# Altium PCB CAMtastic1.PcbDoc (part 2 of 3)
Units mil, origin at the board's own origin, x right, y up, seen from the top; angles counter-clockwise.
Board outline 2031.62 x 893.83 mil, 4 copper layers (Top Layer, Mid-Layer 1, Mid-Layer 2, Bottom Layer); 0 components, 63 nets, 248 pads, 0 vias.
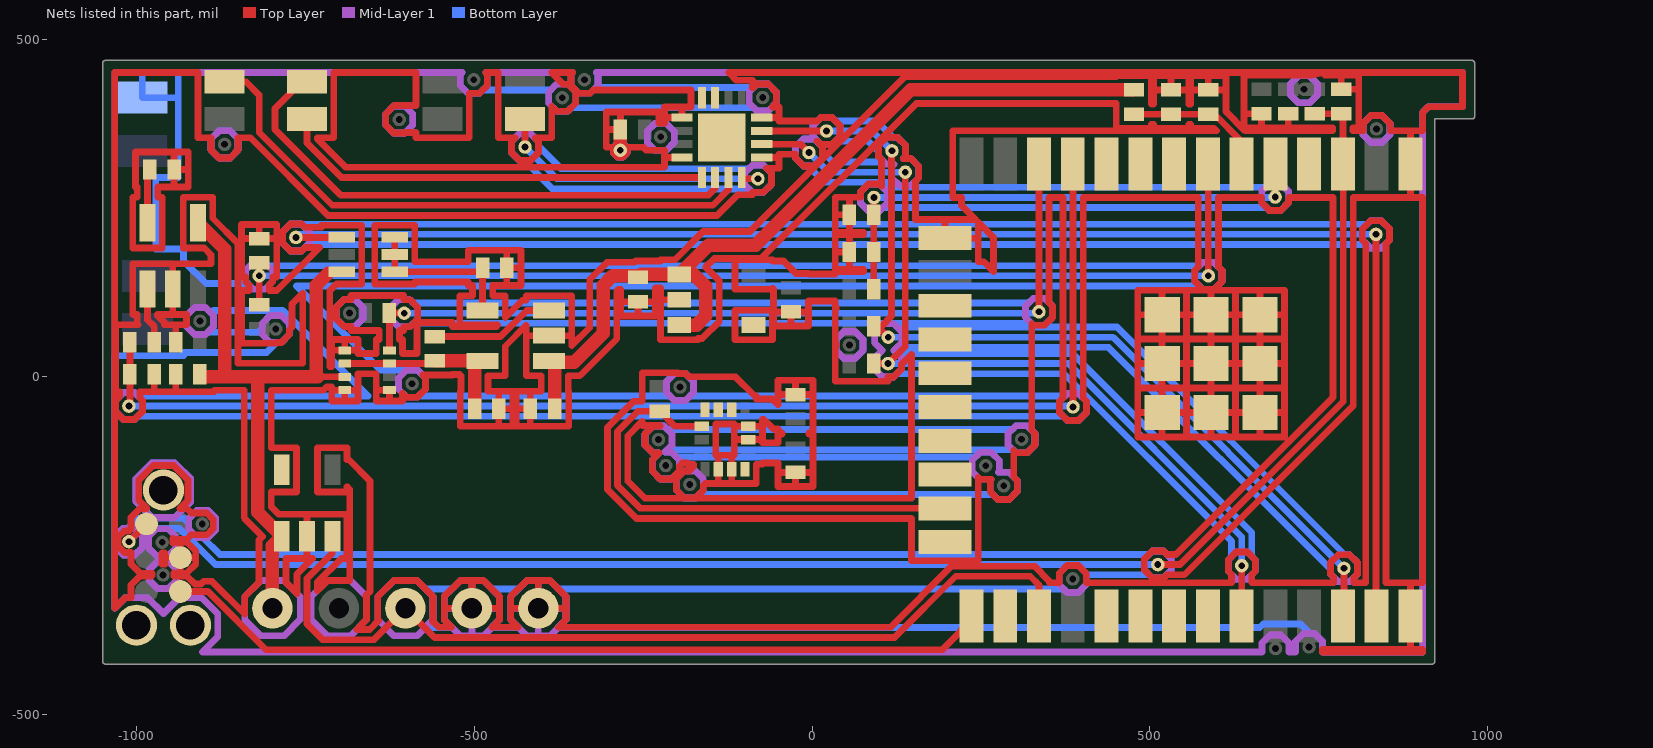
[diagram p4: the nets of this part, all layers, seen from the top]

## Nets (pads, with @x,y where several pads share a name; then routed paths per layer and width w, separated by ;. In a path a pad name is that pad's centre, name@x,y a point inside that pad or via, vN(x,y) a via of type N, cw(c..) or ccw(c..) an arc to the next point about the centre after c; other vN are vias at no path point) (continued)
$Net11: pad.1@55.12,184.98 pad.1@55.12,240.1 pad.1@196.46,205.31 pad.1@518.11,19.68 pad.1@518.11,92.13 pad.1@518.11,-52.76 pad.1@531.44,424.91 pad.1@586.55,424.91 pad.1@590.55,19.68 pad.1@590.55,92.13 pad.1@590.55,-52.76 pad.1@662.99,19.68 pad.1@662.99,92.13 pad.1@662.99,-52.76 pad.1@665.35,389.76 pad.1@704.72,389.76 pad.1@783.46,425.76 pad.1@885.83,314.96 pad.1@885.83,-354.33 pad.1@-24.8,-26.2 pad.1@-24.8,-141.51 pad.1@-31.5,96.17 pad.1@-74.8,324.8 pad.1@-74.8,383.86 pad.1@-94.49,-73.23 pad.1@-94.49,-92.91 pad.1@-119.29,-137.01 pad.1@-138.98,-137.01 pad.1@-192.91,324.8 pad.1@-192.91,383.86 pad.1@-196.85,114.17 pad.1@-257.87,111.13 pad.1@-284.03,366.14 pad.1@-284.16,335.43 pad.1@-389.76,61.02 pad.1@-405.51,-342.52 pad.1@-417.32,-47.24 pad.1@-452.19,161.42 pad.1@-464,-47.24 pad.1@-503.94,-342.52 pad.1@-625.98,-19.69 pad.1@-692.13,39.37 pad.1@-692.13,-19.69 pad.1@-748.03,-236.22 pad.1@-818.9,204.72 pad.1@-935.63,-267.72 pad.1@-942.55,3.94 pad.1@-942.55,51.18 pad.1@-944.88,307.09 pad.1@-946.85,129.92 pad.1@-974.18,3.94 pad.1@-992.13,413.39 | length 81681.8
  Top Layer w10: -974.18,-17.06 pad.1@-974.18,3.94 ; -953.56,-267.72 pad.1@-935.63,-267.72 ; -946.85,97.36 pad.1@-946.85,129.92 -946.85,162.48 ; -944.88,286.09 pad.1@-944.88,307.09 ; -944.88,328.09 pad.1@-944.88,307.09 ; -942.55,-17.06 pad.1@-942.55,3.94 ; pad.1@-942.55,51.18 -942.55,72.18 ; -935.63,-285.65 pad.1@-935.63,-267.72 ; -935.63,-249.79 pad.1@-935.63,-267.72 ; -928.88,307.09 pad.1@-944.88,307.09 ; -917.7,-267.72 pad.1@-935.63,-267.72 ; -890.08,335.98 -890.08,354.17 -909.61,354.17 -909.61,450.57 -1032.68,450.57 -1032.68,-342.47 -1017.41,-327.21 -1008.56,-327.21 -1008.56,-308.22 -995.13,-294.79 -978.26,-294.79 -977.23,-293.75 -977.23,-290.65 -995.13,-290.65 -1008.56,-277.21 -1008.56,-260.09 -1018.44,-260.09 -1027.81,-250.72 -1027.81,-237.47 -1018.44,-228.09 -1011.56,-228.09 -1008.56,-225.09 -1008.56,-208.22 -995.13,-194.79 -985.19,-194.79 -997.14,-182.84 -997.14,-152.59 -975.75,-131.21 -945.51,-131.21 -924.12,-152.59 -924.12,-182.84 -936.07,-194.79 -926.13,-194.79 -919.2,-201.72 -896.51,-201.72 -887.06,-211.16 -887.06,-224.42 -896.43,-233.79 -909.69,-233.79 -909.76,-233.72 -919.2,-233.72 -926.13,-240.65 -945.13,-240.65 -946.48,-239.29 -946.48,-246.14 -945.13,-244.79 -926.13,-244.79 -912.7,-258.22 -912.7,-277.21 -926.13,-290.65 -945.13,-290.65 -945.23,-290.55 -945.23,-294.89 -945.13,-294.79 -926.13,-294.79 -914.2,-306.72 -905.09,-306.72 -901.09,-302.72 -888.67,-302.72 -840.21,-351.17 -840.21,-325.54 -819.21,-304.54 -819.21,-241.72 -813.72,-236.22 -841.15,-208.78 -841.15,-20 -885.55,-20 -885.55,-22.06 -995.18,-22.06 -995.18,-31.65 -991.81,-35.02 -991.81,-51.59 -1003.53,-63.31 -1020.1,-63.31 -1031.81,-51.59 -1031.81,-35.02 -1025.18,-28.39 -1025.18,-22.06 -1031.18,-22.06 -1031.18,77.18 -998.21,77.18 -999.34,78.31 -999.34,92.36 -1006.06,92.36 -1006.06,167.48 -890.08,167.48 -890.08,180.69 -900.17,190.79 -931.26,190.79 -931.26,265.91 -887.64,265.91 -887.64,234.82 -850.08,197.26 -850.08,20 -754.46,20 -754.46,123.81 -770.31,107.95 -770.31,73.68 -774.34,69.65 -774.34,62.58 -786.05,50.87 -792.9,50.87 -792.9,49.87 -844.9,49.87 -844.9,127.87 -833.9,127.87 -833.9,136.32 -838.9,141.32 -838.9,147.72 -844.9,147.72 -844.9,225.72 -792.9,225.72 -792.9,147.72 -798.9,147.72 -798.9,141.32 -803.9,136.32 -803.9,127.87 -792.9,127.87 -792.9,127.79 -729.2,191.49 -751.22,191.49 -756.22,186.49 -772.78,186.49 -784.5,198.2 -784.5,214.77 -772.78,226.48 -756.22,226.48 -751.22,221.48 -726.53,221.48 -726.53,224.57 -667.17,224.57 -667.17,137.64 -704.16,137.64 -714.46,127.34 -714.46,15 -711.57,15 -711.57,55.28 -672.68,55.28 -672.68,34.68 -645.43,34.68 -645.43,55.28 -640.98,55.28 -640.98,68.49 -682.98,68.49 -682.98,74.49 -693.32,74.49 -705.04,86.2 -705.04,102.77 -693.32,114.49 -682.98,114.49 -682.98,120.49 -604.98,120.49 -604.98,114.25 -595.84,114.25 -584.13,102.53 -584.13,85.96 -595.84,74.25 -604.98,74.25 -604.98,68.49 -610.98,68.49 -610.98,55.28 -606.54,55.28 -606.54,34.68 -585.05,34.68 -585.05,80.62 -533.06,80.62 -533.06,74.7 -467.61,74.7 -465.7,76.61 -521.81,76.61 -521.81,120.24 -503.19,120.24 -503.19,135.42 -509.19,135.42 -509.19,140.51 -588.43,140.51 -588.43,137.64 -647.79,137.64 -647.79,224.57 -588.43,224.57 -588.43,170.51 -509.19,170.51 -509.19,187.42 -431.19,187.42 -431.19,135.42 -473.19,135.42 -473.19,120.24 -454.57,120.24 -454.57,87.75 -428.89,113.42 -423.39,113.42 -423.39,120.24 -356.14,120.24 -356.14,46.16 -329.44,72.86 -329.44,144.05 -303.89,169.61 -263.54,169.61 -261.57,171.57 -224.57,171.57 -224.57,173.39 -203.32,173.39 -161.49,215.21 -92.1,215.21 137.6,444.91 450.32,444.91 450.32,445.91 502.32,445.91 502.32,403.91 505.44,403.91 505.44,445.91 557.44,445.91 557.44,403.91 560.55,403.91 560.55,445.91 612.55,445.91 612.55,392.91 641.13,364.33 770.83,364.33 770.83,368.76 639.35,368.76 639.35,446.76 739.73,446.76 754.64,450.57 -123.51,450.57 -112.08,439.13 -88.43,439.13 -88.43,428.39 -86.93,428.39 -81.69,433.63 -65.12,433.63 -53.4,421.91 -53.4,405.34 -58.98,399.76 -49.06,399.76 -49.06,379.01 7.99,379.01 12.99,384.01 29.56,384.01 41.28,372.29 41.28,355.72 29.56,344.01 12.99,344.01 7.99,349.01 6.67,349.01 15.23,340.45 15.23,323.89 3.51,312.17 -13.06,312.17 -24.77,323.89 -24.77,329.49 -49.06,329.49 -49.06,308.9 -67.66,308.9 -60.36,301.6 -60.36,285.04 -72.08,273.32 -88.43,273.32 -88.43,269.53 -110.41,269.53 -140.89,239.05 -716.95,239.05 -832.08,354.17 -850.08,354.17 -850.08,352.55 ; -890.06,335.97 -878.35,324.25 -861.78,324.25 -850.06,335.97 -850.06,352.53 ; -839.9,204.72 pad.1@-818.9,204.72 ; -818.9,220.72 pad.1@-818.9,204.72 ; -797.9,204.72 pad.1@-818.9,204.72 ; -748.03,-263.86 pad.1@-748.03,-236.22 -748.03,-208.58 ; -706.57,-19.69 pad.1@-692.13,-19.69 ; -706.57,39.37 pad.1@-692.13,39.37 ; -692.13,-30.59 pad.1@-692.13,-19.69 ; -692.13,50.28 pad.1@-692.13,39.37 ; -677.68,-19.69 pad.1@-692.13,-19.69 ; -677.68,39.37 pad.1@-692.13,39.37 ; -640.43,-19.69 pad.1@-625.98,-19.69 -625.98,-30.59 ; -539.94,-342.52 pad.1@-503.94,-342.52 ; -503.94,-306.52 pad.1@-503.94,-342.52 ; -467.94,-342.52 pad.1@-503.94,-342.52 ; -464,-68.24 pad.1@-464,-47.24 ; -464,-26.24 pad.1@-464,-47.24 ; -452.19,140.42 pad.1@-452.19,161.42 ; -452.19,182.42 pad.1@-452.19,161.42 ; -448,-47.24 pad.1@-464,-47.24 ; -441.51,-342.52 pad.1@-405.51,-342.52 ; -436.19,161.42 pad.1@-452.19,161.42 ; -433.32,-47.24 pad.1@-417.32,-47.24 ; -418.39,61.02 pad.1@-389.76,61.02 -361.14,61.02 ; -417.32,-68.24 pad.1@-417.32,-47.24 ; -417.32,-26.24 pad.1@-417.32,-47.24 ; -405.51,-306.52 pad.1@-405.51,-342.52 ; -369.51,-342.52 pad.1@-405.51,-342.52 ; -300.03,366.14 pad.1@-284.03,366.14 -284.03,387.14 ; -278.87,111.13 pad.1@-257.87,111.13 ; -257.87,95.13 pad.1@-257.87,111.13 ; -236.87,111.13 pad.1@-257.87,111.13 ; -219.57,114.17 pad.1@-196.85,114.17 ; -213.66,324.8 pad.1@-192.91,324.8 ; -213.66,383.86 pad.1@-192.91,383.86 -192.91,394.76 ; -138.98,-152.83 pad.1@-138.98,-137.01 -138.98,-121.18 ; -119.29,-152.83 pad.1@-119.29,-137.01 -119.29,-121.18 ; -110.31,-92.91 pad.1@-94.49,-92.91 -78.66,-92.91 ; -110.31,-73.23 pad.1@-94.49,-73.23 -78.66,-73.23 ; pad.1@-74.8,324.8 -54.06,324.8 ; pad.1@-74.8,383.86 -54.06,383.86 ; -52.5,96.17 pad.1@-31.5,96.17 ; -45.8,-141.51 pad.1@-24.8,-141.51 ; -45.8,-26.2 pad.1@-24.8,-26.2 ; -31.5,80.17 pad.1@-31.5,96.17 ; -24.8,-157.51 pad.1@-24.8,-141.51 ; -24.8,-10.21 pad.1@-24.8,-26.2 ; -10.5,96.17 pad.1@-31.5,96.17 ; -3.8,-141.51 pad.1@-24.8,-141.51 ; -3.8,-26.2 pad.1@-24.8,-26.2 ; 39.12,184.98 pad.1@55.12,184.98 ; 39.12,240.1 pad.1@55.12,240.1 ; 55.12,163.98 pad.1@55.12,184.98 ; 55.12,205.98 pad.1@55.12,184.98 ; 55.12,219.1 pad.1@55.12,240.1 ; 55.12,261.1 pad.1@55.12,240.1 ; 196.46,228.03 pad.1@196.46,205.31 240.83,205.31 ; 486.93,-52.76 pad.1@518.11,-52.76 ; 486.93,19.68 pad.1@518.11,19.68 ; 486.93,92.13 pad.1@518.11,92.13 ; 510.44,424.91 pad.1@531.44,424.91 ; 518.11,-83.94 pad.1@518.11,-52.76 ; 518.11,-21.58 pad.1@518.11,-52.76 ; 518.11,-11.5 pad.1@518.11,19.68 ; 518.11,50.87 pad.1@518.11,19.68 ; 518.11,60.95 pad.1@518.11,92.13 ; 518.11,123.31 pad.1@518.11,92.13 ; 531.44,440.91 pad.1@531.44,424.91 ; 549.29,-52.76 pad.1@518.11,-52.76 ; 549.29,19.68 pad.1@518.11,19.68 ; 549.29,92.13 pad.1@518.11,92.13 ; 552.44,424.91 pad.1@531.44,424.91 ; 559.37,-52.76 pad.1@590.55,-52.76 ; 559.37,19.68 pad.1@590.55,19.68 ; 559.37,92.13 pad.1@590.55,92.13 ; 565.55,424.91 pad.1@586.55,424.91 ; 586.55,440.91 pad.1@586.55,424.91 ; 590.55,-83.94 pad.1@590.55,-52.76 ; 590.55,-21.58 pad.1@590.55,-52.76 ; 590.55,-11.5 pad.1@590.55,19.68 ; 590.55,50.87 pad.1@590.55,19.68 ; 590.55,60.95 pad.1@590.55,92.13 ; 590.55,123.31 pad.1@590.55,92.13 ; 607.55,424.91 pad.1@586.55,424.91 ; 621.73,-52.76 pad.1@590.55,-52.76 ; 621.73,19.68 pad.1@590.55,19.68 ; 621.73,92.13 pad.1@590.55,92.13 ; 631.81,-52.76 pad.1@662.99,-52.76 ; 631.81,19.68 pad.1@662.99,19.68 ; 631.81,92.13 pad.1@662.99,92.13 ; 644.35,389.76 pad.1@665.35,389.76 665.35,373.76 ; 662.99,-83.94 pad.1@662.99,-52.76 ; 662.99,-21.58 pad.1@662.99,-52.76 ; 662.99,-11.5 pad.1@662.99,19.68 ; 662.99,50.87 pad.1@662.99,19.68 ; 662.99,60.95 pad.1@662.99,92.13 ; 662.99,123.31 pad.1@662.99,92.13 ; 694.17,-52.76 pad.1@662.99,-52.76 ; 694.17,19.68 pad.1@662.99,19.68 ; 694.17,92.13 pad.1@662.99,92.13 ; 704.72,373.76 pad.1@704.72,389.76 ; 783.46,441.76 pad.1@783.46,425.76 804.46,425.76 ; 885.83,-398.7 pad.1@885.83,-354.33 885.83,-309.96 ; 885.83,270.59 pad.1@885.83,314.96 885.83,359.33 ; -1006.06,190.79 -1006.06,265.91 -999.25,265.91 -999.25,281.09 -1001.88,281.09 -1001.88,333.09 -923.88,333.09 -923.88,281.09 -969.25,281.09 -969.25,265.91 -962.44,265.91 -962.44,190.79 -1006.06,190.79 ; -969.34,90.74 -969.34,92.36 -926.55,92.36 -926.55,90.96 -926.55,77.18 -959.18,77.18 -959.18,80.58 -969.34,90.74 ; -962.79,-277.31 -962.7,-277.21 -962.7,-260.91 -958.56,-260.91 -958.56,-277.21 -958.47,-277.31 -962.79,-277.31 ; -801.15,-192.22 -801.15,-170.43 -763.62,-170.43 -763.62,-105.16 -801.15,-105.16 -801.15,-20 -724,-20 -719,-15 -711.57,-15 -711.57,-35.59 -672.68,-35.59 -672.68,4.69 -645.43,4.69 -645.43,-35.59 -606.54,-35.59 -606.54,-24.24 -600.75,-30.03 -584.18,-30.03 -572.46,-18.31 -572.46,-1.74 -576.83,2.62 -533.06,2.62 -533.06,3.62 -521.81,3.62 -521.81,1.81 -520,1.81 -520,-21.24 -521,-21.24 -521,-73.24 -443,-73.24 -443,-21.24 -480,-21.24 -480,1.81 -454.57,1.81 -454.57,45.32 -423.39,76.51 -423.39,1.81 -401.32,1.81 -401.32,-21.24 -438.32,-21.24 -438.32,-73.24 -360.32,-73.24 -360.32,-21.24 -361.32,-21.24 -361.32,1.65 -344.08,1.65 -289.44,56.29 -289.44,127.48 -287.32,129.61 -283.87,129.61 -283.87,90.13 -231.87,90.13 -231.87,131.58 -224.57,131.58 -224.57,54.96 -169.13,54.96 -169.13,56.77 -162.98,56.77 -137.48,82.27 -137.48,142.14 -157.74,162.4 -144.93,175.21 -75.53,175.21 154.17,404.91 450.32,404.91 450.32,403.91 450.32,367.91 502.32,367.91 502.32,373.91 505.44,373.91 505.44,367.91 557.44,367.91 557.44,373.91 560.55,373.91 560.55,367.91 595.13,367.91 598.71,364.33 208.11,364.33 208.11,265.59 221.22,265.59 221.22,253.63 241.82,233.03 152.79,233.03 152.79,289.87 157.79,294.87 157.79,311.43 146.08,323.15 134.9,323.15 138.11,326.36 138.11,342.93 126.39,354.65 109.83,354.65 98.11,342.93 98.11,326.36 102.56,321.91 102.56,282.79 99.75,285.6 83.18,285.6 71.47,273.88 71.47,266.1 34.12,266.1 34.12,214.1 76.12,214.1 76.12,210.98 34.12,210.98 34.12,158.98 76.12,158.98 76.12,155.86 34.12,155.86 34.12,152.17 -5.5,152.17 -5.5,153.17 -24.21,153.17 -42.61,171.57 -58.9,171.57 -58.9,173.39 -114.33,173.39 -114.33,129.76 -58.9,129.76 -58.9,131.29 -57.5,129.89 -57.5,75.17 -5.5,75.17 -5.5,112.17 34.12,112.17 34.12,103.86 35.12,103.86 35.12,100.74 34.12,100.74 34.12,48.74 35.12,48.74 35.12,45.62 34.12,45.62 34.12,-6.37 112.12,-6.37 112.12,-0.37 120.61,-0.37 132.33,11.34 132.33,18.41 147.09,33.17 147.09,-179.69 -247.92,-179.69 -273.15,-154.46 -273.15,-87.39 -251.72,-65.96 -251.59,-65.96 -251.59,-71.96 -225.8,-71.96 -224.91,-72.85 -235.93,-72.85 -247.65,-84.56 -247.65,-101.13 -235.93,-112.85 -226.72,-112.85 -236.87,-122.99 -236.87,-139.56 -225.15,-151.27 -208.58,-151.27 -196.87,-139.56 -196.87,-132.49 -191.98,-127.6 -184.61,-127.6 -184.61,-129.49 -175.55,-129.49 -175.55,-132.68 -182.18,-139.32 -189.55,-139.32 -201.26,-151.03 -201.26,-167.6 -189.55,-179.32 -172.98,-179.32 -161.26,-167.6 -161.26,-160.82 -158.28,-157.83 -82.72,-157.83 -82.72,-129.49 -73.66,-129.49 -73.66,-127.6 -50.8,-127.6 -50.8,-162.51 1.2,-162.51 1.2,-84.51 -4.8,-84.51 -4.8,-83.2 1.2,-83.2 1.2,-5.21 -50.8,-5.21 -50.8,-41.23 -59.29,-32.75 -82.72,-32.75 -82.72,-27.99 -85.31,-27.99 -113.28,-0.01 -182.43,-0.01 -187.48,5.04 -199.59,5.04 -199.59,6.04 -251.59,6.04 -251.59,-35.96 -264.15,-35.96 -303.15,-74.96 -303.15,-166.88 -260.35,-209.68 147.09,-209.68 147.09,-272.4 245.83,-272.4 245.83,-148.92 248.62,-151.72 264.88,-151.72 263.46,-153.13 263.46,-169.7 275.18,-181.42 291.75,-181.42 303.46,-169.7 303.46,-153.13 298.46,-148.13 298.46,-109.16 301.75,-112.45 318.32,-112.45 330.04,-100.73 330.04,-84.16 325.04,-79.16 325.04,78.74 327.37,76.4 343.94,76.4 355.66,88.11 355.66,104.68 350.66,109.68 350.66,265.59 371.19,265.59 371.19,-31.18 366.19,-36.18 366.19,-52.75 377.91,-64.46 394.48,-64.46 406.19,-52.75 406.19,-36.18 401.19,-31.18 401.19,265.59 571.61,265.59 571.61,162.89 566.61,157.89 566.61,141.32 578.33,129.61 594.9,129.61 606.61,141.32 606.61,157.89 601.61,162.89 601.61,265.59 665.53,265.59 665.53,258.04 677.25,246.32 693.82,246.32 705.53,258.04 705.53,265.59 771.32,265.59 771.32,-30.3 538.62,-263 525.1,-263 520.1,-258 503.53,-258 491.81,-269.72 491.81,-286.29 503.53,-298 520.1,-298 525.1,-293 551.05,-293 801.32,-42.73 801.32,265.59 903.89,265.59 903.89,-304.96 849.65,-304.96 849.65,197.7 854.65,202.7 854.65,219.27 842.93,230.98 826.36,230.98 814.65,219.27 814.65,202.7 819.65,197.7 819.65,-304.96 802.4,-304.96 802.4,-296.75 807.4,-291.75 807.4,-275.18 795.69,-263.46 779.12,-263.46 767.4,-275.18 767.4,-291.75 772.4,-296.75 772.4,-304.96 651.01,-304.96 651.01,-292.81 656.01,-287.81 656.01,-271.24 644.3,-259.53 627.73,-259.53 616.02,-271.24 616.02,-287.81 621.02,-292.81 621.02,-304.96 405.83,-304.96 405.83,-290.93 394.11,-279.21 377.54,-279.21 365.83,-290.93 365.83,-304.96 350.83,-304.96 350.83,-302.05 329.05,-280.28 206.39,-280.28 115.83,-370.83 -375.84,-370.83 -364.51,-359.5 -364.51,-325.54 -388.53,-301.52 -422.49,-301.52 -446.51,-325.54 -446.51,-359.5 -435.19,-370.83 -474.26,-370.83 -462.94,-359.5 -462.94,-325.54 -486.95,-301.52 -520.92,-301.52 -544.94,-325.54 -544.94,-359.5 -533.61,-370.83 -552.84,-370.83 -562.76,-360.9 -561.36,-359.5 -561.36,-325.54 -585.38,-301.52 -619.34,-301.52 -643.36,-325.54 -643.36,-359.5 -641.96,-360.9 -655.21,-374.15 -674.44,-374.15 -659.79,-359.5 -659.79,-325.54 -661.19,-324.13 -654.74,-317.68 -654.74,-154.25 -686.19,-122.8 -688.82,-122.8 -688.82,-105.16 -732.44,-105.16 -732.44,-170.43 -688.82,-170.43 -688.82,-162.59 -684.74,-166.67 -684.74,-301.52 -717.77,-301.52 -733.03,-316.78 -733.03,-304.6 -697.29,-268.86 -688.82,-268.86 -688.82,-203.58 -789.79,-203.58 -801.15,-192.22 ; -779.21,-304.54 -779.21,-268.86 -739.72,-268.86 -763.03,-292.17 -763.03,-320.72 -779.21,-304.54 ; -733.03,352.67 -733.03,354.17 -708.5,354.17 -708.5,450.57 -586.77,450.57 -586.77,401.89 -619,401.89 -619.81,401.09 -631.52,389.37 -631.52,372.8 -619.81,361.09 -603.24,361.09 -602.44,361.89 -586.77,361.89 -586.77,354.17 -507.72,354.17 -507.72,419.92 -492.82,419.92 -481.11,431.63 -481.11,448.2 -483.47,450.57 -464.72,450.57 -464.72,354.17 -440.21,354.17 -440.21,353.61 -445.21,348.61 -445.21,332.04 -433.49,320.32 -416.92,320.32 -405.21,332.04 -405.21,348.61 -410.21,353.61 -410.21,354.17 -385.67,354.17 -385.67,400.69 -378.36,393.39 -361.79,393.39 -350.08,405.1 -350.08,421.67 -361.79,433.39 -368.87,433.39 -385.67,450.19 -385.67,450.57 -354.94,450.57 -357.31,448.2 -357.31,431.63 -345.59,419.92 -329.02,419.92 -324.02,424.92 -179.29,424.92 -179.29,399.76 -218.66,399.76 -218.66,375.38 -227.03,375.38 -227.03,392.14 -305.03,392.14 -305.03,340.14 -293.6,340.14 -294.16,339.58 -294.16,331.29 -288.3,325.43 -280.02,325.43 -274.16,331.29 -274.16,339.58 -274.73,340.14 -250.32,340.14 -245.55,335.38 -218.66,335.38 -218.66,310.28 -690.64,310.28 -733.03,352.67 ; -142.95,-116.18 -142.95,-69.65 -115.31,-69.65 -115.31,-90.12 -115.31,-116.18 -142.95,-116.18 ; -114.33,54.96 -114.33,98.58 -58.9,98.58 -58.9,54.96 -114.33,54.96 ; -73.66,-97.6 -73.66,-62.75 -71.71,-62.75 -61.65,-72.81 -57.26,-77.2 -50.8,-77.2 -50.8,-83.2 -44.8,-83.2 -44.8,-84.51 -50.8,-84.51 -50.8,-97.6 -73.66,-97.6 ; 245.83,170.39 245.83,229.02 268.46,206.39 268.46,156.03 254.1,170.39 245.83,170.39 ; 481.93,-88.94 554.29,-88.94 554.29,-16.58 481.93,-16.58 481.93,-88.94 ; 481.93,-16.5 554.29,-16.5 554.29,55.87 481.93,55.87 481.93,-16.5 ; 481.93,55.95 554.29,55.95 554.29,128.31 481.93,128.31 481.93,55.95 ; 554.37,-88.94 626.73,-88.94 626.73,-16.58 554.37,-16.58 554.37,-88.94 ; 554.37,-16.5 626.73,-16.5 626.73,55.87 554.37,55.87 554.37,-16.5 ; 554.37,55.95 626.73,55.95 626.73,128.31 554.37,128.31 554.37,55.95 ; 626.81,-88.94 699.17,-88.94 699.17,-16.58 626.81,-16.58 626.81,-88.94 ; 626.81,-16.5 699.17,-16.5 699.17,55.87 626.81,55.87 626.81,-16.5 ; 626.81,55.95 699.17,55.95 699.17,128.31 626.81,128.31 626.81,55.95 ; 755.7,-407.26 755.7,-403.7 903.89,-403.7 903.89,-407.26 755.7,-407.26 ; 756.65,450.57 962.94,450.57 962.94,399.83 912.09,399.83 903.89,391.63 903.89,364.33 855.83,364.33 855.83,375.11 855.5,375.44 843.79,387.15 827.22,387.15 815.5,375.44 815.5,364.33 800.83,364.33 800.83,368.76 809.46,368.76 809.46,446.76 759.01,446.76 756.65,450.57
  Top Layer w20: pad.1@-284.16,335.43 -284.03,335.56 pad.1@-284.03,366.14
  Mid-Layer 1 w10: -539.94,-342.52 pad.1@-503.94,-342.52 ; -503.94,-378.52 pad.1@-503.94,-342.52 ; -503.94,-306.52 pad.1@-503.94,-342.52 ; -467.94,-342.52 pad.1@-503.94,-342.52 ; -441.51,-342.52 pad.1@-405.51,-342.52 ; -405.51,-378.52 pad.1@-405.51,-342.52 ; -405.51,-306.52 pad.1@-405.51,-342.52 ; -369.51,-342.52 pad.1@-405.51,-342.52 ; -1032.68,-342.47 -1032.68,450.57 -518.74,450.57 -521.11,448.2 -521.11,431.63 -509.39,419.92 -492.82,419.92 -481.11,431.63 -481.11,448.2 -483.47,450.57 -354.94,450.57 -357.31,448.2 -357.31,431.63 -345.59,419.92 -329.02,419.92 -317.31,431.63 -317.31,448.2 -319.67,450.57 962.94,450.57 962.94,399.83 912.09,399.83 903.89,391.63 903.89,-407.26 755.7,-407.26 755.7,-391.55 743.99,-379.84 727.42,-379.84 715.7,-391.55 715.7,-407.26 706.04,-407.26 706.04,-393.99 694.33,-382.28 677.76,-382.28 666.04,-393.99 666.04,-407.26 -902.88,-407.26 -880.12,-384.5 -880.12,-350.94 -903.85,-327.21 -937.41,-327.21 -960.63,-350.42 -983.85,-327.21 -1017.41,-327.21 -1032.68,-342.47 ; -1031.81,-252.38 -1020.1,-264.09 -1003.53,-264.09 -991.81,-252.38 -991.81,-235.81 -1003.53,-224.09 -1020.1,-224.09 -1031.81,-235.81 -1031.81,-252.38 ; -1031.81,-51.59 -1020.1,-63.31 -1003.53,-63.31 -991.81,-51.59 -991.81,-35.02 -1003.53,-23.31 -1020.1,-23.31 -1031.81,-35.02 -1031.81,-51.59 ; -1001.14,-184.5 -977.41,-208.23 -943.85,-208.23 -920.12,-184.5 -920.12,-150.94 -943.85,-127.21 -977.41,-127.21 -1001.14,-150.94 -1001.14,-184.5 ; -982.48,-253.19 -970.76,-264.91 -954.19,-264.91 -942.48,-253.19 -942.48,-236.62 -954.19,-224.91 -970.76,-224.91 -982.48,-236.62 -982.48,-253.19 ; -981.23,-301.59 -969.51,-313.31 -952.94,-313.31 -941.23,-301.59 -941.23,-285.02 -952.94,-273.31 -969.51,-273.31 -981.23,-285.02 -981.23,-301.59 ; -926.55,74.39 -914.84,62.68 -898.27,62.68 -886.55,74.39 -886.55,90.96 -898.27,102.68 -914.84,102.68 -926.55,90.96 -926.55,74.39 ; -923.06,-226.08 -911.34,-237.79 -894.78,-237.79 -883.06,-226.08 -883.06,-209.51 -894.78,-197.79 -911.34,-197.79 -923.06,-209.51 -923.06,-226.08 ; -890.06,335.97 -878.35,324.25 -861.78,324.25 -850.06,335.97 -850.06,352.53 -861.78,364.25 -878.35,364.25 -890.06,352.53 -890.06,335.97 ; -840.21,-359.5 -816.2,-383.52 -782.23,-383.52 -758.21,-359.5 -758.21,-325.54 -782.23,-301.52 -816.2,-301.52 -840.21,-325.54 -840.21,-359.5 ; -838.9,141.32 -827.18,129.61 -810.61,129.61 -798.9,141.32 -798.9,157.89 -810.61,169.61 -827.18,169.61 -838.9,157.89 -838.9,141.32 ; -814.33,62.58 -802.62,50.87 -786.05,50.87 -774.34,62.58 -774.34,79.15 -786.05,90.87 -802.62,90.87 -814.33,79.15 -814.33,62.58 ; -784.5,198.2 -772.78,186.49 -756.22,186.49 -744.5,198.2 -744.5,214.77 -756.22,226.48 -772.78,226.48 -784.5,214.77 -784.5,198.2 ; -741.79,-359.5 -717.77,-383.52 -683.8,-383.52 -659.79,-359.5 -659.79,-325.54 -683.8,-301.52 -717.77,-301.52 -741.79,-325.54 -741.79,-359.5 ; -705.04,86.2 -693.32,74.49 -676.76,74.49 -665.04,86.2 -665.04,102.77 -676.76,114.49 -693.32,114.49 -705.04,102.77 -705.04,86.2 ; -643.36,-359.5 -619.34,-383.52 -585.38,-383.52 -561.36,-359.5 -561.36,-325.54 -585.38,-301.52 -619.34,-301.52 -643.36,-325.54 -643.36,-359.5 ; -631.52,372.8 -619.81,361.09 -603.24,361.09 -591.52,372.8 -591.52,389.37 -603.24,401.09 -619.81,401.09 -631.52,389.37 -631.52,372.8 ; -624.13,85.96 -612.41,74.25 -595.84,74.25 -584.13,85.96 -584.13,102.53 -595.84,114.25 -612.41,114.25 -624.13,102.53 -624.13,85.96 ; -612.46,-18.31 -600.75,-30.03 -584.18,-30.03 -572.46,-18.31 -572.46,-1.74 -584.18,9.97 -600.75,9.97 -612.46,-1.74 -612.46,-18.31 ; -544.94,-359.5 -520.92,-383.52 -486.95,-383.52 -462.94,-359.5 -462.94,-325.54 -486.95,-301.52 -520.92,-301.52 -544.94,-325.54 -544.94,-359.5 ; -446.51,-359.5 -422.49,-383.52 -388.53,-383.52 -364.51,-359.5 -364.51,-325.54 -388.53,-301.52 -422.49,-301.52 -446.51,-325.54 -446.51,-359.5 ; -445.21,332.04 -433.49,320.32 -416.92,320.32 -405.21,332.04 -405.21,348.61 -416.92,360.32 -433.49,360.32 -445.21,348.61 -445.21,332.04 ; -390.08,405.1 -378.36,393.39 -361.79,393.39 -350.08,405.1 -350.08,421.67 -361.79,433.39 -378.36,433.39 -390.08,421.67 -390.08,405.1 ; -294.16,331.29 -288.3,325.43 -280.02,325.43 -274.16,331.29 -274.16,339.58 -280.02,345.43 -288.3,345.43 -294.16,339.58 -294.16,331.29 ; -247.65,-101.13 -247.65,-84.56 -235.93,-72.85 -219.36,-72.85 -207.65,-84.56 -207.65,-101.13 -217.79,-111.27 -208.58,-111.27 -196.87,-122.99 -196.87,-139.56 -208.58,-151.27 -225.15,-151.27 -236.87,-139.56 -236.87,-122.99 -226.72,-112.85 -235.93,-112.85 -247.65,-101.13 ; -244.41,347.09 -232.69,335.38 -216.13,335.38 -204.41,347.09 -204.41,363.66 -216.13,375.38 -232.69,375.38 -244.41,363.66 -244.41,347.09 ; -215.71,-23.3 -204,-35.01 -187.43,-35.01 -175.71,-23.3 -175.71,-6.73 -187.43,4.99 -204,4.99 -215.71,-6.73 -215.71,-23.3 ; -201.26,-167.6 -189.55,-179.32 -172.98,-179.32 -161.26,-167.6 -161.26,-151.03 -172.98,-139.32 -189.55,-139.32 -201.26,-151.03 -201.26,-167.6 ; -100.36,285.04 -88.65,273.32 -72.08,273.32 -60.36,285.04 -60.36,301.6 -72.08,313.32 -88.65,313.32 -100.36,301.6 -100.36,285.04 ; -93.4,405.34 -81.69,393.63 -65.12,393.63 -53.4,405.34 -53.4,421.91 -65.12,433.63 -81.69,433.63 -93.4,421.91 -93.4,405.34 ; -24.77,323.89 -13.06,312.17 3.51,312.17 15.23,323.89 15.23,340.45 3.51,352.17 -13.06,352.17 -24.77,340.45 -24.77,323.89 ; 1.28,355.72 12.99,344.01 29.56,344.01 41.28,355.72 41.28,372.29 29.56,384.01 12.99,384.01 1.28,372.29 1.28,355.72 ; 35.12,38.96 46.83,27.24 63.4,27.24 75.12,38.96 75.12,55.53 63.4,67.24 46.83,67.24 35.12,55.53 35.12,38.96 ; 71.47,257.32 83.18,245.6 99.75,245.6 111.46,257.32 111.46,273.88 99.75,285.6 83.18,285.6 71.47,273.88 71.47,257.32 ; 92.33,11.34 92.33,27.91 103.69,39.27 92.48,50.48 92.48,67.05 104.2,78.77 120.76,78.77 132.48,67.05 132.48,50.48 121.12,39.12 132.33,27.91 132.33,11.34 120.61,-0.37 104.05,-0.37 92.33,11.34 ; 98.11,326.36 98.11,342.93 109.83,354.65 126.39,354.65 138.11,342.93 138.11,326.36 134.9,323.15 146.08,323.15 157.79,311.43 157.79,294.87 146.08,283.15 129.51,283.15 117.8,294.87 117.8,311.43 121.01,314.65 109.83,314.65 98.11,326.36 ; 236.91,-140 236.91,-123.43 248.62,-111.72 265.19,-111.72 276.91,-123.43 276.91,-140 275.49,-141.42 291.75,-141.42 303.46,-153.13 303.46,-169.7 291.75,-181.42 275.18,-181.42 263.46,-169.7 263.46,-153.13 264.88,-151.72 248.62,-151.72 236.91,-140 ; 290.04,-100.73 301.75,-112.45 318.32,-112.45 330.04,-100.73 330.04,-84.16 318.32,-72.45 301.75,-72.45 290.04,-84.16 290.04,-100.73 ; 315.66,88.11 327.37,76.4 343.94,76.4 355.66,88.11 355.66,104.68 343.94,116.4 327.37,116.4 315.66,104.68 315.66,88.11 ; 365.83,-307.5 377.54,-319.21 394.11,-319.21 405.83,-307.5 405.83,-290.93 394.11,-279.21 377.54,-279.21 365.83,-290.93 365.83,-307.5 ; 366.19,-52.75 377.91,-64.46 394.48,-64.46 406.19,-52.75 406.19,-36.18 394.48,-24.46 377.91,-24.46 366.19,-36.18 366.19,-52.75 ; 491.81,-286.29 503.53,-298 520.1,-298 531.81,-286.29 531.81,-269.72 520.1,-258 503.53,-258 491.81,-269.72 491.81,-286.29 ; 566.61,141.32 578.33,129.61 594.9,129.61 606.61,141.32 606.61,157.89 594.9,169.61 578.33,169.61 566.61,157.89 566.61,141.32 ; 616.02,-287.81 627.73,-299.53 644.3,-299.53 656.01,-287.81 656.01,-271.24 644.3,-259.53 627.73,-259.53 616.02,-271.24 616.02,-287.81 ; 665.53,258.04 677.25,246.32 693.82,246.32 705.53,258.04 705.53,274.61 693.82,286.32 677.25,286.32 665.53,274.61 665.53,258.04 ; 708.35,417.48 720.06,405.76 736.63,405.76 748.35,417.48 748.35,434.05 736.63,445.76 720.06,445.76 708.35,434.05 708.35,417.48 ; 767.4,-291.75 779.12,-303.46 795.69,-303.46 807.4,-291.75 807.4,-275.18 795.69,-263.46 779.12,-263.46 767.4,-275.18 767.4,-291.75 ; 814.65,202.7 826.36,190.98 842.93,190.98 854.65,202.7 854.65,219.27 842.93,230.98 826.36,230.98 814.65,219.27 814.65,202.7 ; 815.5,358.87 827.22,347.15 843.79,347.15 855.5,358.87 855.5,375.44 843.79,387.15 827.22,387.15 815.5,375.44 815.5,358.87
  Bottom Layer w10: -992.13,448.01 pad.1@-992.13,413.39 -943.72,413.39 ; -539.94,-342.52 pad.1@-503.94,-342.52 -467.94,-342.52 ; -441.51,-342.52 pad.1@-405.51,-342.52 -369.51,-342.52 ; -1032.68,-342.47 -1032.68,31.24 -930.85,31.24 -930.85,36.18 -807.81,36.18 -793.12,50.87 -786.05,50.87 -774.34,62.58 -774.34,79.15 -786.05,90.87 -802.62,90.87 -814.33,79.15 -814.33,72.08 -820.23,66.18 -894.77,66.18 -886.55,74.39 -886.55,98.11 -783.87,98.11 -657.46,-28.31 -998.53,-28.31 -1003.53,-23.31 -1020.1,-23.31 -1031.81,-35.02 -1031.81,-51.59 -1020.1,-63.31 -1003.53,-63.31 -998.53,-58.31 371.76,-58.31 377.91,-64.46 394.48,-64.46 406.19,-52.75 406.19,-36.18 394.48,-24.46 377.91,-24.46 374.06,-28.31 -180.72,-28.31 -175.71,-23.3 -175.71,-6.73 -187.43,4.99 -204,4.99 -215.71,-6.73 -215.71,-23.3 -210.7,-28.31 -582.46,-28.31 -572.46,-18.31 -572.46,-1.74 -584.18,9.97 -639.17,9.97 -763.8,134.61 573.33,134.61 578.33,129.61 594.9,129.61 606.61,141.32 606.61,157.89 594.9,169.61 578.33,169.61 573.33,164.61 -805.61,164.61 -810.61,169.61 -827.18,169.61 -838.9,157.89 -838.9,141.32 -835.68,138.11 -897.23,138.11 -928.72,169.61 -930.85,169.61 -930.85,189.23 -972.13,189.23 -972.13,295.02 -938.72,295.02 -938.72,450.57 -518.74,450.57 -521.11,448.2 -521.11,431.63 -509.39,419.92 -492.82,419.92 -487.82,424.92 -386.83,424.92 -390.08,421.67 -390.08,405.1 -378.36,393.39 -361.79,393.39 -356.55,398.63 -86.69,398.63 -81.69,393.63 -65.12,393.63 -53.4,405.34 -53.4,421.91 -65.12,433.63 -81.69,433.63 -86.69,428.63 -320.31,428.63 -317.31,431.63 -317.31,448.2 -319.67,450.57 962.94,450.57 962.94,399.83 912.09,399.83 903.89,391.63 903.89,-407.26 755.7,-407.26 755.7,-391.55 743.99,-379.84 736.92,-379.84 723.07,-365.99 667.92,-365.99 662.68,-371.23 -376.24,-371.23 -364.51,-359.5 -364.51,-325.54 -375.84,-314.21 372.54,-314.21 377.54,-319.21 394.11,-319.21 405.83,-307.5 405.83,-293 498.53,-293 503.53,-298 520.1,-298 531.81,-286.29 531.81,-269.72 520.1,-258 503.53,-258 498.53,-263 -877.2,-263 -902.41,-237.79 -894.78,-237.79 -883.06,-226.08 -883.06,-209.51 -894.78,-197.79 -911.34,-197.79 -923.06,-209.51 -923.06,-217.15 -930.79,-209.41 -998.34,-209.41 -1013.02,-224.09 -1020.1,-224.09 -1031.81,-235.81 -1031.81,-252.38 -1020.1,-264.09 -1003.53,-264.09 -991.81,-252.38 -991.81,-245.31 -985.91,-239.41 -982.48,-239.41 -982.48,-253.19 -970.76,-264.91 -963.39,-264.91 -955,-273.31 -969.51,-273.31 -981.23,-285.02 -981.23,-301.59 -969.51,-313.31 -952.94,-313.31 -947.94,-308.31 -941.18,-308.31 -922.28,-327.21 -937.41,-327.21 -960.63,-350.42 -983.85,-327.21 -1017.41,-327.21 -1032.68,-342.47 ; -1001.14,-184.5 -977.41,-208.23 -943.85,-208.23 -920.12,-184.5 -920.12,-150.94 -943.85,-127.21 -977.41,-127.21 -1001.14,-150.94 -1001.14,-184.5 ; -890.06,335.97 -878.35,324.25 -861.78,324.25 -850.06,335.97 -850.06,352.53 -861.78,364.25 -878.35,364.25 -890.06,352.53 -890.06,335.97 ; -784.5,198.2 -784.5,214.77 -772.78,226.48 -756.22,226.48 -755.71,225.98 821.36,225.98 826.36,230.98 842.93,230.98 854.65,219.27 854.65,202.7 842.93,190.98 826.36,190.98 821.36,195.98 -746.72,195.98 -756.22,186.49 -772.78,186.49 -784.5,198.2 ; -705.04,86.2 -693.32,74.49 -676.76,74.49 -665.04,86.2 -665.04,102.77 -676.76,114.49 -693.32,114.49 -705.04,102.77 -705.04,86.2 ; -631.52,372.8 -619.81,361.09 -603.24,361.09 -591.52,372.8 -591.52,389.37 -603.24,401.09 -619.81,401.09 -631.52,389.37 -631.52,372.8 ; -624.13,85.96 -624.13,102.53 -612.41,114.25 -595.84,114.25 -590.84,109.25 320.22,109.25 327.37,116.4 343.94,116.4 355.66,104.68 355.66,88.11 343.94,76.4 327.37,76.4 324.52,79.25 -590.84,79.25 -595.84,74.25 -612.41,74.25 -624.13,85.96 ; -573.09,-371.23 -561.36,-359.5 -561.36,-325.54 -572.69,-314.21 -533.61,-314.21 -544.94,-325.54 -544.94,-359.5 -533.21,-371.23 -573.09,-371.23 ; -474.66,-371.23 -462.94,-359.5 -462.94,-325.54 -474.26,-314.21 -435.19,-314.21 -446.51,-325.54 -446.51,-359.5 -434.78,-371.23 -474.66,-371.23 ; -445.21,332.04 -445.21,348.61 -433.49,360.32 -416.92,360.32 -405.21,348.61 -405.21,341.54 -371.99,308.32 -93.65,308.32 -88.65,313.32 -72.08,313.32 -60.36,301.6 -60.36,285.04 -72.08,273.32 -88.65,273.32 -93.65,278.32 -384.42,278.32 -426.42,320.32 -433.49,320.32 -445.21,332.04 ; -294.16,331.29 -288.3,325.43 -280.02,325.43 -274.16,331.29 -274.16,339.58 -280.02,345.43 -288.3,345.43 -294.16,339.58 -294.16,331.29 ; -247.65,-101.13 -247.65,-84.56 -235.93,-72.85 -219.36,-72.85 -214.36,-77.85 296.35,-77.85 301.75,-72.45 318.32,-72.45 330.04,-84.16 330.04,-100.73 318.32,-112.45 301.75,-112.45 297.15,-107.85 -214.36,-107.85 -217.79,-111.27 -208.58,-111.27 -201,-118.86 241.48,-118.86 248.62,-111.72 265.19,-111.72 276.91,-123.43 276.91,-140 275.49,-141.42 291.75,-141.42 303.46,-153.13 303.46,-169.7 291.75,-181.42 275.18,-181.42 268.08,-174.32 -167.98,-174.32 -172.98,-179.32 -189.55,-179.32 -201.26,-167.6 -201.26,-151.03 -199.09,-148.86 -206.17,-148.86 -208.58,-151.27 -225.15,-151.27 -236.87,-139.56 -236.87,-122.99 -226.72,-112.85 -235.93,-112.85 -247.65,-101.13 ; -244.41,347.09 -232.69,335.38 -216.13,335.38 -204.41,347.09 -204.41,363.66 -216.13,375.38 -232.69,375.38 -244.41,363.66 -244.41,347.09 ; -24.77,323.89 -24.77,340.45 -13.06,352.17 3.51,352.17 15.23,340.45 15.23,333.38 30.46,318.15 106.32,318.15 98.11,326.36 98.11,333.43 82.53,349.01 34.56,349.01 29.56,344.01 12.99,344.01 1.28,355.72 1.28,372.29 12.99,384.01 29.56,384.01 34.56,379.01 94.96,379.01 119.32,354.65 126.39,354.65 138.11,342.93 138.11,326.36 134.9,323.15 146.08,323.15 157.79,311.43 157.79,294.87 146.08,283.15 129.51,283.15 124.51,288.15 18.04,288.15 -5.98,312.17 -13.06,312.17 -24.77,323.89 ; 35.12,38.96 46.83,27.24 63.4,27.24 75.12,38.96 75.12,55.53 63.4,67.24 46.83,67.24 35.12,55.53 35.12,38.96 ; 71.47,257.32 71.47,273.88 83.18,285.6 99.75,285.6 104.75,280.6 671.52,280.6 677.25,286.32 693.82,286.32 705.53,274.61 705.53,258.04 693.82,246.32 677.25,246.32 672.97,250.6 104.75,250.6 99.75,245.6 83.18,245.6 71.47,257.32 ; 92.33,11.34 92.33,27.91 103.69,39.27 92.48,50.48 92.48,67.05 104.2,78.77 120.76,78.77 125.76,73.77 451.38,73.77 788.61,-263.46 795.69,-263.46 807.4,-275.18 807.4,-291.75 795.69,-303.46 779.12,-303.46 767.4,-291.75 767.4,-284.68 438.96,43.77 125.76,43.77 121.12,39.12 125.61,34.62 385.53,34.62 651.01,-230.86 651.01,-266.24 656.01,-271.24 656.01,-287.81 644.3,-299.53 627.73,-299.53 616.02,-287.81 616.02,-271.24 621.02,-266.24 621.02,-243.29 373.1,4.63 125.61,4.63 120.61,-0.37 104.05,-0.37 92.33,11.34 ; 708.35,417.48 720.06,405.76 736.63,405.76 748.35,417.48 748.35,434.05 736.63,445.76 720.06,445.76 708.35,434.05 708.35,417.48 ; 815.5,358.87 827.22,347.15 843.79,347.15 855.5,358.87 855.5,375.44 843.79,387.15 827.22,387.15 815.5,375.44 815.5,358.87
$Net12: pad.1@834.65,210.98 pad.1@835.83,-354.33 pad.1@-696.85,206.69 pad.1@-764.5,206.49 | length 2234.5
  Top Layer w10: pad.1@-764.5,206.49 -697.06,206.49 pad.1@-696.85,206.69 ; pad.1@834.65,210.98 834.65,-353.15 pad.1@835.83,-354.33
  Bottom Layer w10: pad.1@-764.5,206.49 -760,210.98 pad.1@834.65,210.98
$Net13: pad.1@385.83,314.96 pad.1@386.19,-44.46 pad.1@-1010.18,3.94 pad.1@-1010.18,51.18 pad.1@-1011.81,-43.31 | length 1853.2
  Top Layer w10: pad.1@-1011.81,-43.31 -1010.18,-41.68 pad.1@-1010.18,3.94 pad.1@-1010.18,51.18 ; pad.1@385.83,314.96 386.19,314.59 pad.1@386.19,-44.46
  Bottom Layer w10: pad.1@-1011.81,-43.31 385.04,-43.31 pad.1@386.19,-44.46
$Net14: pad.1@585.83,314.96 pad.1@586.61,149.61 pad.1@-818.9,106.87 pad.1@-818.9,149.61 pad.1@-818.9,168.72 | length 1633.1
  Top Layer w10: pad.1@-818.9,106.87 pad.1@-818.9,149.61 pad.1@-818.9,168.72 ; pad.1@585.83,314.96 586.61,314.17 pad.1@586.61,149.61
  Bottom Layer w10: pad.1@-818.9,149.61 pad.1@586.61,149.61
$Net15: pad.1@335.66,96.4 pad.1@335.83,314.96 pad.1@-604.13,94.25 pad.1@-625.98,39.37 pad.1@-625.98,94.49 | length 1236.4
  Top Layer w10: pad.1@-625.98,39.37 pad.1@-625.98,94.49 -604.37,94.49 pad.1@-604.13,94.25 ; pad.1@335.66,96.4 335.66,314.79 pad.1@335.83,314.96
  Bottom Layer w10: pad.1@-604.13,94.25 333.51,94.25 pad.1@335.66,96.4
$Net16: pad.1@-80.36,293.32 pad.1@-104.33,295.28 pad.1@-425.2,381.89 pad.1@-425.21,340.32 | length 430.7
  Top Layer w10: pad.1@-425.21,340.32 pad.1@-425.21,381.88 ; pad.1@-104.33,295.28 -102.38,293.32 pad.1@-80.36,293.32
  Bottom Layer w10: pad.1@-425.21,340.32 -378.2,293.32 pad.1@-80.36,293.32
$Net17: pad.1@91.12,129.86 pad.1@91.12,184.98 pad.1@91.12,240.1 pad.1@91.47,265.6 pad.1@685.53,266.32 pad.1@685.83,314.96 | length 779
  Top Layer w10: pad.1@91.12,129.86 pad.1@91.12,184.98 pad.1@91.12,240.1 91.12,265.25 pad.1@91.47,265.6 ; pad.1@685.53,266.32 685.53,314.67 pad.1@685.83,314.96
  Bottom Layer w10: pad.1@91.47,265.6 684.81,265.6 pad.1@685.53,266.32
$Net18: pad.1@91.12,19.63 pad.1@112.33,19.63 pad.1@137.8,303.15 pad.1@635.83,-354.33 pad.1@636.01,-279.53 pad.1@-4.77,332.17 pad.1@-74.8,344.49 | length 1292.4
  Top Layer w10: pad.1@-74.8,344.49 -17.09,344.49 pad.1@-4.77,332.17 ; pad.1@91.12,19.63 pad.1@112.33,19.63 137.8,45.09 pad.1@137.8,303.15 ; pad.1@635.83,-354.33 636.01,-354.14 pad.1@636.01,-279.53
  Bottom Layer w10: pad.1@-4.77,332.17 24.25,303.15 pad.1@137.8,303.15 ; pad.1@112.33,19.63 379.32,19.63 636.01,-237.07 pad.1@636.01,-279.53
$Net19: pad.1@21.28,364.01 pad.1@91.12,74.74 pad.1@112.48,58.77 pad.1@118.11,334.65 pad.1@785.83,-354.33 pad.1@787.4,-283.46 pad.1@-74.8,364.17 | length 1393.6
  Top Layer w10: pad.1@-74.8,364.17 -74.64,364.01 pad.1@21.28,364.01 ; pad.1@91.12,74.74 pad.1@96.5,74.74 ; pad.1@112.48,58.77 pad.1@96.5,74.74 ; pad.1@118.11,334.65 117.56,334.09 117.56,90 102.3,74.74 pad.1@96.5,74.74 ; pad.1@785.83,-354.33 787.4,-352.76 pad.1@787.4,-283.46
  Bottom Layer w10: pad.1@21.28,364.01 88.75,364.01 pad.1@118.11,334.65 ; pad.1@112.48,58.77 445.17,58.77 pad.1@787.4,-283.46
$Net20: pad.1@511.81,-278 pad.1@744.09,389.76 pad.1@783.46,389.76 pad.1@785.83,314.96 pad.1@-985.63,-217.72 pad.1@-1011.81,-244.09 | length 2432.6
  Top Layer w10: pad.1@-1011.81,-244.09 -1011.81,-243.9 pad.1@-985.63,-217.72 ; pad.1@511.81,-278 544.83,-278 786.32,-36.51 786.32,314.47 pad.1@785.83,314.96 785.83,387.4 pad.1@783.46,389.76 pad.1@744.09,389.76
  Bottom Layer w10: pad.1@-1011.81,-244.09 -992.13,-224.41 -937.01,-224.41 -883.42,-278 pad.1@511.81,-278
$Net21: pad.1@-960.63,-167.72
$Net22: pad.1@-1000.63,-367.72
$Net23: pad.1@-920.63,-367.72
$Net24: pad.1@-692.13,0 pad.1@-696.85,155.51 pad.1@-785.43,-236.22 pad.1@-799.21,-342.52 pad.1@-906.55,3.94 pad.1@-909.45,228.35 | length 1005.2
  Top Layer w10: -732.28,0 pad.1@-692.13,0 ; -716.54,153.54 -714.57,155.51 pad.1@-696.85,155.51
  Top Layer w20: pad.1@-909.45,228.35 -870.08,188.98 -870.08,0 ; pad.1@-906.55,3.94 -902.62,0 -870.08,0 ; pad.1@-799.21,-342.52 -799.21,-250 pad.1@-785.43,-236.22 -821.15,-200.5 -821.15,0 ; -732.28,0 -734.46,0 ; -716.54,153.54 -734.46,135.62 -734.46,0 ; -870.08,0 -821.15,0 ; -821.15,0 -799.21,0 -734.46,0
$Net25: pad.1@335.83,-354.33 pad.1@-602.36,-342.52 pad.1@-710.63,-236.22 | length 1365
  Top Layer w10: pad.1@-710.63,-236.22 -710.63,-260.98 -748.03,-298.38 -748.03,-366.14 -725.02,-389.15 -648.99,-389.15 pad.1@-602.36,-342.52 -559.06,-385.83 122.05,-385.83 212.6,-295.28 322.83,-295.28 335.83,-308.27 pad.1@335.83,-354.33
$Net26: pad.1@476.32,388.91 pad.1@531.44,388.91 pad.1@586.55,388.91 pad.1@635.83,314.96 | length 209.7
  Top Layer w10: pad.1@476.32,388.91 pad.1@531.44,388.91 582.68,388.91 583.53,388.91 pad.1@586.55,388.91 595.34,388.91 635.83,348.43 pad.1@635.83,314.96
$Net27: pad.1@196.46,-194.69 pad.1@-163.78,-73.23 pad.1@-225.59,-50.96 | length 724.3
  Top Layer w10: pad.1@-163.78,-73.23 -203.32,-73.23 pad.1@-225.59,-50.96 -257.93,-50.96 -288.15,-81.18 -288.15,-160.67 -254.13,-194.69 pad.1@196.46,-194.69
$Net28: pad.1@235.83,-354.33 pad.1@-935.63,-317.72 | length 1230.1
  Top Layer w10: pad.1@-935.63,-317.72 -894.88,-317.72 -808.45,-404.15 192.47,-404.15 218.11,-378.51 pad.1@235.83,-354.33
$Net29: pad.1@-124.02,295.28 pad.1@-870.08,437.01 | length 881.8
  Top Layer w10: pad.1@-870.08,437.01 -838.58,437.01 -818.9,417.32 -818.9,362.2 -710.74,254.05 -147.11,254.05 -124.02,277.14 pad.1@-124.02,295.28
$Net30: pad.1@-163.39,295.28 pad.1@-748.03,381.89 | length 641.3
  Top Layer w10: pad.1@-748.03,381.89 -748.03,346.46 -696.85,295.28 pad.1@-163.39,295.28
$Net31: pad.1@-143.7,295.28 pad.1@-748.03,437.01 | length 807.4
  Top Layer w10: pad.1@-748.03,437.01 -755.78,437.01 -795.28,397.52 -795.28,366.14 -698.17,269.04 -153.28,269.04 -143.7,278.62 pad.1@-143.7,295.28
$Net32: pad.1@-974.18,51.18 pad.1@-984.25,129.92 | length 83
  Top Layer w10: pad.1@-984.25,129.92 -984.34,129.83 -984.34,84.52 -974.18,74.36 pad.1@-974.18,51.18
$Net33: pad.1@-980.88,307.09 pad.1@-984.25,228.35 | length 80.1
  Top Layer w10: pad.1@-984.25,228.35 -984.25,303.72 pad.1@-980.88,307.09
$Net34: pad.1@476.32,424.91 pad.1@-196.85,76.77 pad.1@-196.85,151.57 pad.1@-257.87,147.13 pad.1@-381.32,-47.24 pad.1@-389.76,23.62 | length 1286.5
  Top Layer w20: pad.1@-389.76,23.62 pad.1@-387.8,21.65 ; pad.1@-381.32,-47.24 -381.32,15.18 pad.1@-387.8,21.65 ; pad.1@-257.87,147.13 pad.1@-255.28,149.61 ; pad.1@-254.69,149.61 pad.1@-255.28,149.61 ; pad.1@-196.85,76.77 -171.26,76.77 -157.48,90.55 -157.48,133.86 -175.2,151.57 pad.1@-196.85,151.57 ; pad.1@476.32,424.91 145.88,424.91 -83.81,195.21 -153.21,195.21 pad.1@-196.85,151.57 ; pad.1@-387.8,21.65 -352.36,21.65 -309.44,64.57 -309.44,135.77 -295.6,149.61 pad.1@-255.28,149.61 ; pad.1@-255.28,149.61 -254.69,150.17 -253.29,151.57 pad.1@-196.85,151.57
$Net35: pad.1@-488.19,23.62 pad.1@-500,-47.24 pad.1@-559.06,23.62 pad.1@-625.98,19.68 pad.1@-692.13,19.68 | length 278.8
  Top Layer w10: pad.1@-692.13,19.68 pad.1@-625.98,19.68 -562.99,19.68 pad.1@-559.06,23.62
  Top Layer w20: pad.1@-559.06,23.62 pad.1@-494.41,23.62 ; pad.1@-500,-47.24 -500,18.03 pad.1@-494.41,23.62 ; pad.1@-488.19,23.62 pad.1@-494.41,23.62
$Net36: pad.1@-389.76,98.43 pad.1@-559.06,59.62 | length 185.4
  Top Layer w10: pad.1@-559.06,59.62 -558.97,59.7 -461.4,59.7 -422.68,98.43 pad.1@-389.76,98.43
$Net37: pad.1@-488.19,98.43 pad.1@-488.19,161.42 pad.1@-618.11,155.51 pad.1@-618.11,181.1 pad.1@-618.11,206.69 | length 244.9
  Top Layer w10: pad.1@-618.11,206.69 pad.1@-618.11,181.1 pad.1@-618.11,155.51 -490.16,155.51 pad.1@-488.19,157.48 ; pad.1@-488.19,98.43 pad.1@-488.19,157.48 ; pad.1@-488.19,161.42 pad.1@-488.19,157.48
$Net38: pad.1@735.83,314.96
$Net39: pad.1@535.83,314.96
$Net40: pad.1@485.83,314.96
$Net41: pad.1@435.83,314.96
$Net42: pad.1@196.46,105.31
$Net43: pad.1@196.46,55.31
$Net44: pad.1@196.46,5.31
$Net45: pad.1@196.46,-44.69
$Net46: pad.1@196.46,-94.69
$Net47: pad.1@196.46,-144.69
$Net48: pad.1@196.46,-244.69
$Net49: pad.1@285.83,-354.33
$Net50: pad.1@435.83,-354.33
$Net51: pad.1@485.83,-354.33
$Net52: pad.1@535.83,-354.33
$Net53: pad.1@585.83,-354.33
$Net54: pad.1@-143.7,413.39
$Net55: pad.1@-163.39,413.39
$Net56: pad.1@-133.86,354.33
$Net57: pad.1@-99.61,-137.01
$Net58: pad.1@-119.29,-48.82
$Net59: pad.1@-138.98,-48.82
$Net60: pad.1@-158.66,-48.82
$Net61: pad.1@-86.61,76.77
$Net62: pad.1@-785.43,-137.8
copper on no net: | length 23275.6
  Top Layer w8: -1046.68,-421.26 -1046.68,464.57 976.94,464.57 976.94,385.83 917.89,385.83 917.89,-421.26 -1046.68,-421.26
  Mid-Layer 1 w8: -1046.68,-421.26 -1046.68,464.57 976.94,464.57 976.94,385.83 917.89,385.83 917.89,-421.26 -1046.68,-421.26
  Mid-Layer 2 w8: -1046.68,-421.26 -1046.68,464.57 976.94,464.57 976.94,385.83 917.89,385.83 917.89,-421.26 -1046.68,-421.26
  Bottom Layer w8: -1046.68,-421.26 -1046.68,464.57 976.94,464.57 976.94,385.83 917.89,385.83 917.89,-421.26 -1046.68,-421.26

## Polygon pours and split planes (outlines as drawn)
$Net11 on Bottom Layer (solid, pour order 18): -544.94,-325.54 -544.94,-359.5 -533.21,-371.23 -573.09,-371.23 -561.36,-359.5 -561.36,-325.54 -572.69,-314.21 -533.61,-314.21
$Net11 on Bottom Layer (solid, pour order 17): -446.51,-325.54 -446.51,-359.5 -434.78,-371.23 -474.66,-371.23 -462.94,-359.5 -462.94,-325.54 -474.26,-314.21 -435.19,-314.21
no net on Bottom Layer (solid, pour order 16): 37 vertices, not listed, extent 92.33,-303.46 807.4,78.77
no net on Bottom Layer (solid, pour order 15): 35 vertices, not listed, extent -24.77,283.15 157.79,384.01
no net on Bottom Layer (solid, pour order 14): 17 vertices, not listed, extent 71.47,245.6 705.53,286.32
no net on Bottom Layer (solid, pour order 13): 19 vertices, not listed, extent -445.21,273.32 -60.36,360.32
no net on Bottom Layer (solid, pour order 12): 17 vertices, not listed, extent -624.13,74.25 355.66,116.4
no net on Bottom Layer (solid, pour order 11): 17 vertices, not listed, extent -784.5,186.49 854.65,230.98
no net on Bottom Layer (solid, pour order 10): -288.3,325.43 -280.02,325.43 -274.16,331.29 -274.16,339.58 -280.02,345.43 -288.3,345.43 -294.16,339.58 -294.16,331.29
no net on Bottom Layer (solid, pour order 9): 43 vertices, not listed, extent -247.65,-181.42 330.04,-72.45
no net on Bottom Layer (solid, pour order 8): -232.69,335.38 -216.13,335.38 -204.41,347.09 -204.41,363.66 -216.13,375.38 -232.69,375.38 -244.41,363.66 -244.41,347.09
no net on Bottom Layer (solid, pour order 7): -693.32,74.49 -676.76,74.49 -665.04,86.2 -665.04,102.77 -676.76,114.49 -693.32,114.49 -705.04,102.77 -705.04,86.2
no net on Bottom Layer (solid, pour order 6): 46.83,27.24 63.4,27.24 75.12,38.96 75.12,55.53 63.4,67.24 46.83,67.24 35.12,55.53 35.12,38.96
no net on Bottom Layer (solid, pour order 5): -878.35,324.25 -861.78,324.25 -850.06,335.97 -850.06,352.53 -861.78,364.25 -878.35,364.25 -890.06,352.53 -890.06,335.97
no net on Bottom Layer (solid, pour order 4): -619.81,361.09 -603.24,361.09 -591.52,372.8 -591.52,389.37 -603.24,401.09 -619.81,401.09 -631.52,389.37 -631.52,372.8
no net on Bottom Layer (solid, pour order 3): 827.22,347.15 843.79,347.15 855.5,358.87 855.5,375.44 843.79,387.15 827.22,387.15 815.5,375.44 815.5,358.87
no net on Bottom Layer (solid, pour order 2): 720.06,405.76 736.63,405.76 748.35,417.48 748.35,434.05 736.63,445.76 720.06,445.76 708.35,434.05 708.35,417.48
no net on Bottom Layer (solid, pour order 1): -1001.14,-150.94 -1001.14,-184.5 -977.41,-208.23 -943.85,-208.23 -920.12,-184.5 -920.12,-150.94 -943.85,-127.21 -977.41,-127.21
$Net11 on Bottom Layer (solid, pour order 0): 162 vertices, not listed, extent -1032.68,-407.26 962.94,450.57
no net on Mid-Layer 1 (solid, pour order 67): 327.37,76.4 343.94,76.4 355.66,88.12 355.66,104.68 343.94,116.4 327.37,116.4 315.66,104.68 315.66,88.12
no net on Mid-Layer 1 (solid, pour order 66): -612.41,74.25 -595.84,74.25 -584.13,85.96 -584.13,102.53 -595.84,114.25 -612.41,114.25 -624.13,102.53 -624.13,85.96
no net on Mid-Layer 1 (solid, pour order 65): 578.33,129.61 594.9,129.61 606.61,141.32 606.61,157.89 594.9,169.61 578.33,169.61 566.61,157.89 566.61,141.32
no net on Mid-Layer 1 (solid, pour order 64): -827.18,129.61 -810.61,129.61 -798.9,141.32 -798.9,157.89 -810.61,169.61 -827.18,169.61 -838.9,157.89 -838.9,141.32
no net on Mid-Layer 1 (solid, pour order 63): 377.91,-64.46 394.48,-64.46 406.19,-52.75 406.19,-36.18 394.48,-24.46 377.91,-24.46 366.19,-36.18 366.19,-52.75
no net on Mid-Layer 1 (solid, pour order 62): -1020.1,-63.31 -1003.53,-63.31 -991.81,-51.59 -991.81,-35.02 -1003.53,-23.31 -1020.1,-23.31 -1031.81,-35.02 -1031.81,-51.59
no net on Mid-Layer 1 (solid, pour order 61): -772.78,186.49 -756.22,186.49 -744.5,198.2 -744.5,214.77 -756.22,226.48 -772.78,226.48 -784.5,214.77 -784.5,198.2
no net on Mid-Layer 1 (solid, pour order 60): 826.36,190.98 842.93,190.98 854.65,202.7 854.65,219.27 842.93,230.98 826.36,230.98 814.65,219.27 814.65,202.7
no net on Mid-Layer 1 (solid, pour order 59): -288.3,325.43 -280.02,325.43 -274.16,331.29 -274.16,339.58 -280.02,345.43 -288.3,345.43 -294.16,339.58 -294.16,331.29
no net on Mid-Layer 1 (solid, pour order 58): 301.75,-112.45 318.32,-112.45 330.04,-100.73 330.04,-84.16 318.32,-72.45 301.75,-72.45 290.04,-84.16 290.04,-100.73
no net on Mid-Layer 1 (solid, pour order 57): -189.55,-179.32 -172.98,-179.32 -161.26,-167.6 -161.26,-151.03 -172.98,-139.32 -189.55,-139.32 -201.26,-151.03 -201.26,-167.6
no net on Mid-Layer 1 (solid, pour order 56): 17 vertices, not listed, extent 236.91,-181.42 303.46,-111.72
no net on Mid-Layer 1 (solid, pour order 55): 17 vertices, not listed, extent -247.65,-151.27 -196.87,-72.85
no net on Mid-Layer 1 (solid, pour order 54): -970.76,-264.91 -954.19,-264.91 -942.48,-253.19 -942.48,-236.62 -954.19,-224.91 -970.76,-224.91 -982.48,-236.62 -982.48,-253.19
no net on Mid-Layer 1 (solid, pour order 53): -969.51,-313.31 -952.94,-313.31 -941.23,-301.59 -941.23,-285.02 -952.94,-273.31 -969.51,-273.31 -981.23,-285.02 -981.23,-301.59
no net on Mid-Layer 1 (solid, pour order 52): 377.54,-319.21 394.11,-319.21 405.83,-307.5 405.83,-290.93 394.11,-279.21 377.54,-279.21 365.83,-290.93 365.83,-307.5
no net on Mid-Layer 1 (solid, pour order 51): -232.69,335.38 -216.13,335.38 -204.41,347.09 -204.41,363.66 -216.13,375.38 -232.69,375.38 -244.41,363.66 -244.41,347.09
no net on Mid-Layer 1 (solid, pour order 50): -378.36,393.39 -361.79,393.39 -350.08,405.1 -350.08,421.67 -361.79,433.39 -378.36,433.39 -390.08,421.67 -390.08,405.1
no net on Mid-Layer 1 (solid, pour order 49): -81.69,393.63 -65.12,393.63 -53.4,405.34 -53.4,421.91 -65.12,433.63 -81.69,433.63 -93.4,421.91 -93.4,405.34
no net on Mid-Layer 1 (solid, pour order 48): -600.75,-30.03 -584.18,-30.03 -572.46,-18.31 -572.46,-1.74 -584.18,9.97 -600.75,9.97 -612.46,-1.74 -612.46,-18.31
no net on Mid-Layer 1 (solid, pour order 47): -693.32,74.49 -676.76,74.49 -665.04,86.2 -665.04,102.77 -676.76,114.49 -693.32,114.49 -705.04,102.77 -705.04,86.2
no net on Mid-Layer 1 (solid, pour order 46): -802.62,50.87 -786.05,50.87 -774.34,62.58 -774.34,79.15 -786.05,90.87 -802.62,90.87 -814.33,79.15 -814.33,62.58
no net on Mid-Layer 1 (solid, pour order 45): -914.84,62.68 -898.27,62.68 -886.55,74.39 -886.55,90.96 -898.27,102.68 -914.84,102.68 -926.55,90.96 -926.55,74.39
no net on Mid-Layer 1 (solid, pour order 44): 46.83,27.24 63.4,27.24 75.12,38.96 75.12,55.53 63.4,67.24 46.83,67.24 35.12,55.53 35.12,38.96
no net on Mid-Layer 1 (solid, pour order 43): -204,-35.01 -187.43,-35.01 -175.71,-23.3 -175.71,-6.73 -187.43,4.99 -204,4.99 -215.71,-6.73 -215.71,-23.3
no net on Mid-Layer 1 (solid, pour order 42): -911.34,-237.79 -894.78,-237.79 -883.06,-226.08 -883.06,-209.51 -894.78,-197.79 -911.34,-197.79 -923.06,-209.51 -923.06,-226.08
no net on Mid-Layer 1 (solid, pour order 41): -878.35,324.25 -861.78,324.25 -850.06,335.97 -850.06,352.53 -861.78,364.25 -878.35,364.25 -890.06,352.53 -890.06,335.97
no net on Mid-Layer 1 (solid, pour order 40): -619.81,361.09 -603.24,361.09 -591.52,372.8 -591.52,389.37 -603.24,401.09 -619.81,401.09 -631.52,389.37 -631.52,372.8
no net on Mid-Layer 1 (solid, pour order 39): 827.22,347.15 843.79,347.15 855.5,358.87 855.5,375.44 843.79,387.15 827.22,387.15 815.5,375.44 815.5,358.87
no net on Mid-Layer 1 (solid, pour order 38): 720.06,405.76 736.63,405.76 748.35,417.48 748.35,434.05 736.63,445.76 720.06,445.76 708.35,434.05 708.35,417.48
no net on Mid-Layer 1 (solid, pour order 37): -422.49,-383.52 -388.53,-383.52 -364.51,-359.5 -364.51,-325.54 -388.53,-301.52 -422.49,-301.52 -446.51,-325.54 -446.51,-359.5
no net on Mid-Layer 1 (solid, pour order 36): -520.92,-383.52 -486.95,-383.52 -462.94,-359.5 -462.94,-325.54 -486.95,-301.52 -520.92,-301.52 -544.94,-325.54 -544.94,-359.5
no net on Mid-Layer 1 (solid, pour order 35): -619.34,-383.52 -585.38,-383.52 -561.36,-359.5 -561.36,-325.54 -585.38,-301.52 -619.34,-301.52 -643.36,-325.54 -643.36,-359.5
no net on Mid-Layer 1 (solid, pour order 34): -717.77,-383.52 -683.8,-383.52 -659.79,-359.5 -659.79,-325.54 -683.8,-301.52 -717.77,-301.52 -741.79,-325.54 -741.79,-359.5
